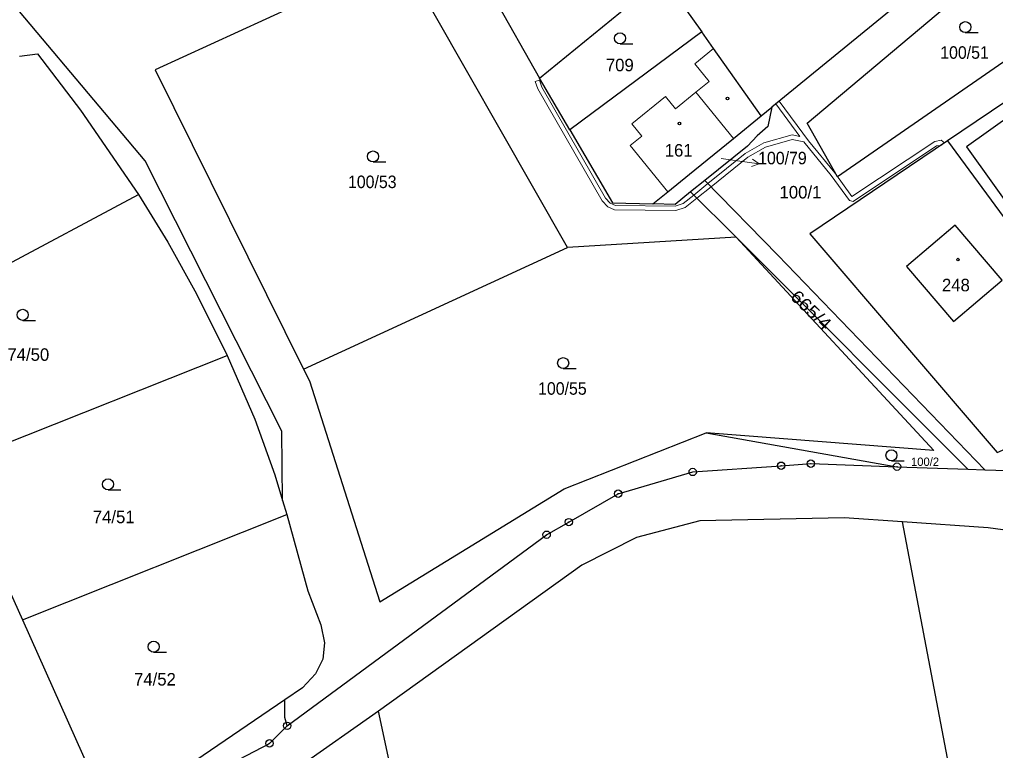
# Model space of a CAD drawing. Extents: x -758887 to -754328, y -1031688 to -1029144.
# Drawn here: x -756312.6 to -756179.9, y -1030649.6 to -1030550.3 of the extents above; entities that cross this region are included whole.
import ezdxf
from ezdxf.enums import TextEntityAlignment as Align

# ---------------------------------------------------------------- set-up
doc = ezdxf.new("R2010")
doc.units = 0
doc.header["$LTSCALE"] = 0.68
for name, color, linetype, lineweight in [('1', 7, 'Continuous', 25), ('13', 7, 'Continuous', 13), ('3', 7, 'Continuous', 25), ('4', 7, 'Continuous', 13), ('5', 7, 'Continuous', 25), ('7', 7, 'Continuous', 13), ('8', 7, 'Continuous', 25)]:
    doc.layers.add(name, color=color, linetype=linetype, lineweight=lineweight)
doc.layers.add('2', color=7, linetype='Continuous')

msp = doc.modelspace()

# ---------------------------------------------------------------- linework, layer by layer
at = {"layer": '1'}
for p, q in [((-756249.73, -1030544.32), (-756241.86, -1030558.24)), ((-756241.86, -1030558.24), (-756225.09, -1030544.5)), ((-756225.09, -1030544.5), (-756219.82, -1030551.93)), ((-756219.82, -1030551.93), (-756237.77, -1030565.23)), ((-756312.59, -1030555.25), (-756310.14, -1030554.94)), ((-756237.77, -1030565.23), (-756241.86, -1030558.24)), ((-756211.74, -1030563.36), (-756210.31, -1030562.19)), ((-756213.62, -1030567.45), (-756219.4, -1030572.13)), ((-756219.4, -1030572.13), (-756221.33, -1030573.69)), ((-756332.11, -1030593.11), (-756296.39, -1030574.02)), ((-756215.16, -1030579.86), (-756221.33, -1030573.69)), ((-756215.16, -1030579.86), (-756238.06, -1030581.25)), ((-756183.66, -1030611.38), (-756215.16, -1030579.86)), ((-756273.96, -1030597.77), (-756238.06, -1030581.25)), ((-756321.68, -1030610.75), (-756284.35, -1030595.91)), ((-756219.24, -1030606.46), (-756193.27, -1030611.04)), ((-756193.27, -1030611.04), (-756183.66, -1030611.38)), ((-756183.66, -1030611.38), (-756181.34, -1030611.46)), ((-756181.34, -1030611.46), (-756175.61, -1030611.67)), ((-756277.87, -1030612.17), (-756276.81, -1030615.63)), ((-756276.81, -1030615.63), (-756276.22, -1030617.55)), ((-756312.2, -1030631.86), (-756300.24, -1030658.53)), ((-756274.11, -1030641.09), (-756276.53, -1030642.74))]:
    msp.add_line(p, q, dxfattribs=at)
for points in [[(-756276.81, -1030615.63), (-756276.9, -1030606.22), (-756295.51, -1030569.46), (-756318.87, -1030541.69)], [(-756238.06, -1030581.25), (-756260.8, -1030541.42), (-756271.57, -1030546.71), (-756294.15, -1030557.1), (-756273.96, -1030597.77)], [(-756156.85, -1030540.84), (-756201.34, -1030571.62), (-756205.5, -1030564.34), (-756186.8, -1030548.66), (-756189.64, -1030545.27)], [(-756189.64, -1030545.27), (-756210.31, -1030562.19), (-756210.84, -1030564.8)], [(-756211.74, -1030563.36), (-756218.22, -1030554.2), (-756219.82, -1030551.93)], [(-756310.14, -1030554.94), (-756304.3, -1030562.56), (-756296.39, -1030574.02)], [(-756226.46, -1030575.33), (-756224.42, -1030573.67), (-756222.73, -1030572.29), (-756220.78, -1030570.71), (-756215.5, -1030566.41), (-756211.74, -1030563.36)], [(-756237.77, -1030565.23), (-756231.94, -1030575.18), (-756226.46, -1030575.33)], [(-756210.84, -1030564.8), (-756212.28, -1030566.07), (-756213.62, -1030567.45)], [(-756186.42, -1030566.76), (-756205.1, -1030579.37), (-756179.64, -1030609.11), (-756161.14, -1030601.04)], [(-756219.4, -1030572.13), (-756209.46, -1030582.31), (-756181.34, -1030611.46)], [(-756296.39, -1030574.02), (-756292.41, -1030580.52), (-756288.51, -1030587.53), (-756284.35, -1030595.91)], [(-756221.33, -1030573.69), (-756223.43, -1030575.39), (-756226.46, -1030575.33)], [(-756215.16, -1030579.86), (-756188.24, -1030608.86), (-756219.24, -1030606.46)], [(-756284.35, -1030595.91), (-756280.61, -1030604.56), (-756277.87, -1030612.17)], [(-756273.96, -1030597.77), (-756273.17, -1030599.37), (-756263.58, -1030629.4), (-756238.51, -1030614.03), (-756219.24, -1030606.46)], [(-756276.19, -1030646.26), (-756240.91, -1030620.29), (-756237.9, -1030618.57), (-756231.18, -1030614.71), (-756221.05, -1030611.76), (-756209.02, -1030610.91), (-756204.99, -1030610.63), (-756193.27, -1030611.04)], [(-756321.68, -1030610.75), (-756312.2, -1030631.86), (-756276.22, -1030617.55)], [(-756276.22, -1030617.55), (-756273.39, -1030627.91), (-756271.63, -1030632.53), (-756271.11, -1030634.98), (-756271.36, -1030637.19), (-756272.34, -1030639.2), (-756274.11, -1030641.09)], [(-756192.51, -1030618.56), (-756200.44, -1030618.01), (-756220.1, -1030618.4), (-756228.7, -1030620.69), (-756236.11, -1030624.42), (-756263.78, -1030644.29)], [(-756252.3, -1030703.63), (-756242.62, -1030754.34), (-756169.3, -1030740.37), (-756192.51, -1030618.56)], [(-756151.84, -1030623.3), (-756180.88, -1030619.37), (-756192.51, -1030618.56)], [(-756276.53, -1030642.74), (-756279.65, -1030644.86), (-756296.45, -1030656.34), (-756300.24, -1030658.53)], [(-756276.19, -1030646.26), (-756276.51, -1030645.14), (-756276.53, -1030642.74)], [(-756263.78, -1030644.29), (-756274.62, -1030651.91), (-756275.93, -1030659.65), (-756266.16, -1030708.47)], [(-756252.3, -1030703.63), (-756251.14, -1030703.23), (-756263.78, -1030644.29)], [(-756283.71, -1030651.34), (-756278.6, -1030648.65), (-756276.19, -1030646.26)]]:
    msp.add_lwpolyline(points, dxfattribs=at)
for points in [[(-756164.69, -1030552.12), (-756186.42, -1030566.76), (-756161.14, -1030601.04), (-756160.01, -1030602.58), (-756141.03, -1030591.62)], [(-756173.65, -1030581.76), (-756167.34, -1030577.28), (-756168.21, -1030576.07), (-756167.24, -1030575.37), (-756170.59, -1030570.65), (-756170.42, -1030570.52), (-756171.12, -1030569.55), (-756172.34, -1030570.32), (-756177.54, -1030563.07), (-756183.82, -1030567.54)], [(-756191.97, -1030583.82), (-756185.58, -1030591.31), (-756178.98, -1030585.7), (-756185.35, -1030578.19)]]:
    msp.add_lwpolyline(points, close=True, dxfattribs=at)
at = {"layer": '13'}
msp.add_lwpolyline([(-756218.98, -1030572.56), (-756220.91, -1030574.11), (-756222.35, -1030575.28), (-756223.44, -1030575.62), (-756231.55, -1030575.52), (-756232.26, -1030575.24), (-756232.9, -1030574.54), (-756241.56, -1030559.43), (-756241.88, -1030558.49), (-756242.45, -1030558.69), (-756242.1, -1030559.67), (-756233.38, -1030574.9), (-756232.6, -1030575.74), (-756231.67, -1030576.12), (-756223.34, -1030576.22), (-756222.07, -1030575.82), (-756220.48, -1030574.54), (-756218.55, -1030572.99), (-756213.56, -1030568.97), (-756211.14, -1030567.6), (-756207.52, -1030566.57), (-756205.92, -1030566.89), (-756202.2, -1030571.45), (-756199.75, -1030574.85), (-756199.21, -1030575), (-756187.88, -1030567.41), (-756187.32, -1030567.37), (-756186.79, -1030567.01), (-756187.27, -1030566.66), (-756188.12, -1030566.85), (-756199.39, -1030574.33), (-756201.74, -1030571.1), (-756205.29, -1030566.76), (-756209.29, -1030561.36), (-756209.74, -1030561.73), (-756206.47, -1030566.17), (-756207.54, -1030565.95), (-756211.38, -1030567.04), (-756213.9, -1030568.47)], close=True, dxfattribs=at)
at = {"layer": '3'}
for p, q in [((-756183.983, -1030552.04), (-756182.233, -1030552.04)), ((-756230.933, -1030553.56), (-756229.183, -1030553.56)), ((-756264.513, -1030569.62), (-756262.763, -1030569.62)), ((-756312.153, -1030591.15), (-756310.403, -1030591.15)), ((-756238.663, -1030597.71), (-756236.913, -1030597.71)), ((-756194.023, -1030610.24), (-756192.273, -1030610.24)), ((-756300.543, -1030614.19), (-756298.793, -1030614.19)), ((-756294.353, -1030636.26), (-756292.603, -1030636.26))]:
    msp.add_line(p, q, dxfattribs=at)
for centre in [(-756183.9829, -1030551.2898), (-756230.9329, -1030552.8098), (-756264.5129, -1030568.8698), (-756312.1529, -1030590.3998), (-756238.6629, -1030596.9598), (-756194.0229, -1030609.4898), (-756300.5429, -1030613.4398), (-756294.3529, -1030635.5098)]:
    msp.add_circle(centre, 0.75, dxfattribs=at)
at = {"layer": '4'}
for p, q in [((-756218.22, -1030554.2), (-756220.78, -1030556.27)), ((-756220.78, -1030556.27), (-756218.82, -1030558.68)), ((-756218.82, -1030558.68), (-756220.61, -1030560.13)), ((-756220.61, -1030560.13), (-756223.4, -1030562.4)), ((-756215.5, -1030566.41), (-756220.61, -1030560.13)), ((-756229.33, -1030564.45), (-756224.76, -1030560.73)), ((-756223.4, -1030562.4), (-756224.76, -1030560.73)), ((-756229.33, -1030564.45), (-756227.98, -1030566.12)), ((-756227.98, -1030566.12), (-756229.53, -1030567.38)), ((-756229.53, -1030567.38), (-756224.42, -1030573.67))]:
    msp.add_line(p, q, dxfattribs=at)
at = {"layer": '5'}
for centre in [(-756216.3168, -1030560.9892), (-756222.8568, -1030564.3992), (-756184.9768, -1030582.8892)]:
    msp.add_circle(centre, 0.175, dxfattribs=at)
at = {"layer": '7'}
msp.add_line((-756211.998, -1030569.878), (-756212.92, -1030569.242), dxfattribs=at)
msp.add_lwpolyline([(-756217.17, -1030569.14), (-756214.97, -1030569.46), (-756211.998, -1030569.878), (-756213.06, -1030570.234)], dxfattribs=at)
at = {"layer": '8'}
for centre, radius in [((-756209.02, -1030610.9099), 0.5), ((-756204.99, -1030610.6299), 0.5), ((-756204.99, -1030610.6299), 0.0303), ((-756193.27, -1030611.0399), 0.5), ((-756221.05, -1030611.7599), 0.5), ((-756221.05, -1030611.7599), 0.0303), ((-756209.02, -1030610.9099), 0.0303), ((-756193.27, -1030611.0399), 0.0303), ((-756231.18, -1030614.7099), 0.5), ((-756231.18, -1030614.7099), 0.0303), ((-756237.9, -1030618.5699), 0.5), ((-756237.9, -1030618.5699), 0.0303), ((-756240.91, -1030620.2899), 0.5), ((-756240.91, -1030620.2899), 0.0303), ((-756276.19, -1030646.2599), 0.5), ((-756276.19, -1030646.2599), 0.0303), ((-756278.6, -1030648.6499), 0.5), ((-756278.6, -1030648.6499), 0.0303)]:
    msp.add_circle(centre, radius, dxfattribs=at)

# ---------------------------------------------------------------- texts
at = {"layer": '2', "width": 0.95}
for s, p in [('100/51', (-756184.089, -1030555.59)), ('100/79', (-756208.849, -1030569.94)), ('100/53', (-756264.619, -1030573.17)), ('100/55', (-756238.769, -1030601.26))]:
    msp.add_text(s, height=1.7, dxfattribs=at).set_placement(p, align=Align.CENTER)
at = {"layer": '2'}
for s, height, p in [('709', 1.7, (-756230.959, -1030557.29)), ('161', 1.7, (-756222.959, -1030568.88)), ('100/1', 1.7, (-756206.4, -1030574.58)), ('248', 1.7, (-756185.259, -1030587.2)), ('74/50', 1.7, (-756311.39, -1030596.65)), ('100/2', 1.14, (-756189.459, -1030610.94)), ('74/51', 1.7, (-756299.78, -1030618.72)), ('74/52', 1.7, (-756294.17, -1030640.79))]:
    msp.add_text(s, height=height, dxfattribs=at).set_placement(p, align=Align.CENTER)
at = {"layer": '2', "width": 1.15}
msp.add_text('665/4', height=1.7, rotation=316, dxfattribs=at).set_placement((-756205.5465, -1030590.3606), align=Align.CENTER)

doc.saveas('drawing.dxf')
